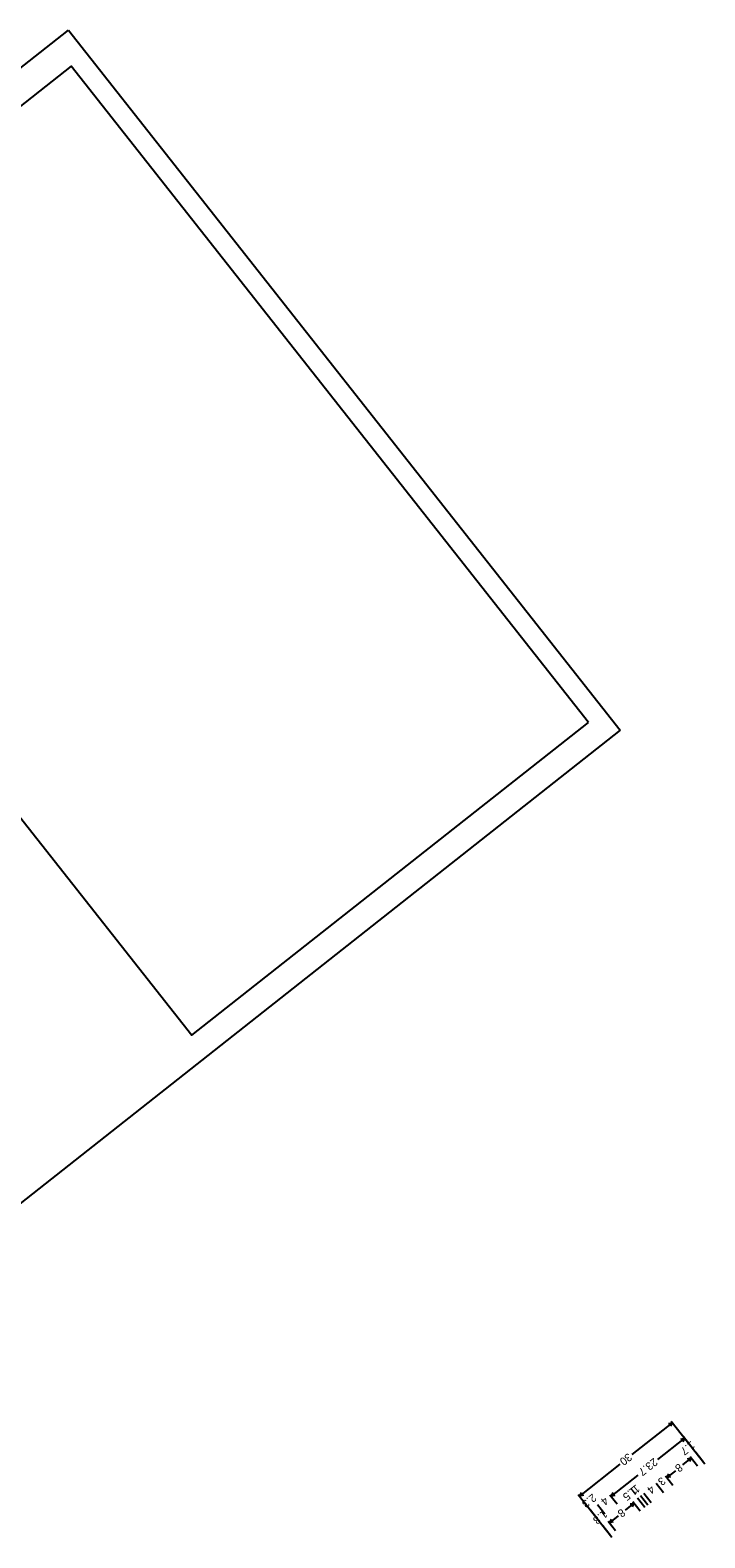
# Model space of a CAD drawing. Extents: x 672126 to 673696, y 1673540 to 1674900.
# Drawn here: x 672375.7 to 672546.6, y 1674518.5 to 1674900.4 of the extents above; entities that cross this region are included whole.
import ezdxf

# ---------------------------------------------------------------- set-up
doc = ezdxf.new("R2010")
doc.units = 0
for name, color, linetype in [('61', 7, 'Continuous'), ('C-ANNO-SYMB', 7, 'Continuous'), ('Level 1', 7, 'Continuous')]:
    doc.layers.add(name, color=color, linetype=linetype)

msp = doc.modelspace()

# ---------------------------------------------------------------- linework, layer by layer
at = {"layer": '61'}
msp.add_lwpolyline([(672517.13, 1674725.06), (672386.09, 1674891.28), (672285.59, 1674812.06), (672416.63, 1674645.83)], close=True, dxfattribs=at)
at = {"layer": 'C-ANNO-SYMB'}
for p, q in [((672528.21, 1674539.62), (672538.44, 1674547.68)), ((672537.46, 1674547.48), (672538.44, 1674547.68)), ((672538.02, 1674546.78), (672538.44, 1674547.68)), ((672538.13, 1674548.08), (672546.64, 1674537.28)), ((672534.73, 1674538.39), (672541.54, 1674543.76)), ((672540.56, 1674543.55), (672541.54, 1674543.76)), ((672541.11, 1674542.85), (672541.54, 1674543.76)), ((672541.23, 1674544.15), (672543.08, 1674541.79)), ((672541.05, 1674537.01), (672543.26, 1674538.75)), ((672542.28, 1674538.54), (672543.26, 1674538.75)), ((672542.83, 1674537.84), (672543.26, 1674538.75)), ((672542.95, 1674539.14), (672544.81, 1674536.78)), ((672542.95, 1674539.14), (672544.81, 1674536.78)), ((672544.32, 1674540.22), (672546.18, 1674537.87)), ((672525.11, 1674537.17), (672514.88, 1674529.11)), ((672539.18, 1674535.53), (672536.98, 1674533.79)), ((672537.4, 1674534.7), (672536.98, 1674533.79)), ((672529.7, 1674534.42), (672522.89, 1674529.05)), ((672534.31, 1674532.33), (672536.17, 1674529.97)), ((672536.67, 1674534.19), (672538.52, 1674531.83)), ((672537.95, 1674534), (672536.98, 1674533.79)), ((672514.57, 1674529.5), (672523.09, 1674518.71)), ((672515.31, 1674530.02), (672514.88, 1674529.11)), ((672515.86, 1674529.31), (672514.88, 1674529.11)), ((672519.43, 1674526.97), (672521.29, 1674524.61)), ((672522.58, 1674529.45), (672524.43, 1674527.09)), ((672522.58, 1674529.45), (672524.43, 1674527.09)), ((672523.31, 1674529.96), (672522.89, 1674529.05)), ((672523.86, 1674529.26), (672522.89, 1674529.05)), ((672526.52, 1674525.55), (672528.73, 1674527.29)), ((672527.75, 1674527.09), (672528.73, 1674527.29)), ((672528.3, 1674526.39), (672528.73, 1674527.29)), ((672528.42, 1674527.69), (672530.28, 1674525.33)), ((672529.6, 1674528.62), (672531.46, 1674526.26)), ((672530.38, 1674529.23), (672532.24, 1674526.88)), ((672531.17, 1674529.85), (672533.03, 1674527.5)), ((672517.67, 1674525.58), (672519.53, 1674523.22)), ((672524.65, 1674524.08), (672522.45, 1674522.34)), ((672522.87, 1674523.25), (672522.45, 1674522.34)), ((672520.76, 1674521.65), (672522.62, 1674519.29)), ((672522.14, 1674522.73), (672524, 1674520.38)), ((672523.43, 1674522.54), (672522.45, 1674522.34))]:
    msp.add_line(p, q, dxfattribs=at)
at = {"layer": 'Level 1'}
for p, q in [((672125.9, 1674695.83), (672385.43, 1674900.44)), ((672385.43, 1674900.44), (672525.22, 1674723.12)), ((672525.22, 1674723.12), (672265.69, 1674518.51))]:
    msp.add_line(p, q, dxfattribs=at)

# ---------------------------------------------------------------- texts
at = {"layer": 'C-ANNO-SYMB'}
for s, p in [('1.7', (672543.18, 1674543.15)), ('30', (672527.2, 1674540.1)), ('23.7', (672533.71, 1674538.86)), ('8', (672540.04, 1674537.48)), ('1.5', (672528.56, 1674531.62)), ('1', (672528.44, 1674531.52)), ('1', (672529.22, 1674532.14)), ('4', (672532.99, 1674531.93)), ('3', (672535.71, 1674534.07)), ('2.3', (672518.19, 1674529.81)), ('4', (672521.26, 1674529.04)), ('1.8', (672521, 1674525.66)), ('8', (672525.51, 1674526.03))]:
    msp.add_text(s, height=2, rotation=218.2508, dxfattribs=at).set_placement(p)

doc.saveas('drawing.dxf')
